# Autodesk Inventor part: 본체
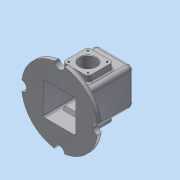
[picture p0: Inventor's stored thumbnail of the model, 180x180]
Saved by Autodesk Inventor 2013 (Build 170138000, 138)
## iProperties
Created: 2018-07
Part Number: 본체
Material: 알루미늄 6061
Document SubType Name: Modeling
Designer: Administrator
Density: 2.71 g/cm^3
Mass: 931.22 g
Surface Area: 1021.53 cm^2
Volume: 343.623 cm^3
Author: Administrator
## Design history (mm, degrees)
sketch "스케치1"
  geometry: C1 r 75 at (0, 0); 1 further point
  constraints: 1 centre point, 1 coincident
  dimensions: "d0" = 150 diameter of C1
extrude "돌출1" new body sketch "스케치1" distance "d1" = 10; taper "d2" = 0 deg
fillet "모깎기1" dims "d9" = 3
sketch "스케치2"
  geometry: C1 r 10 at (0, 75); 1 further point
  constraints: 2 vertical alignment, 1 centre point, 1 other
  dimensions: "d3" = 20 diameter of C1
extrude "돌출2" cut sketch "스케치2" distance "d4" = 10; taper "d5" = 0 deg
sketch "스케치3"
  geometry: L1 (-37, 37)-(37, 37); L2 (37, 37)-(37, -37); L3 (37, -37)-(-37, -37); L4 (-37, -37)-(-37, 37); A1 r 72 centre (0, 0) between (71.393, 9.327) and (9.327, 71.393) reference; A2 r 72 centre (0, 0) between (9.327, -71.393) and (71.393, -9.327) reference; 2 further points
  constraints: 8 end point, 2 midpoint, 2 parallel, 1 horizontal, 1 horizontal alignment, 1 perpendicular, 1 vertical alignment
  dimensions: "d10" = 74 distance of L1.start L1.end; "d12" = 74 distance of L1.end L2.end
extrude "돌출3" join sketch "스케치3" distance "d13" = 100; taper "d14" = 0 deg
sketch "스케치4"
  geometry: L1 (37, 37)-(-37, 37) reference; L2 (37, -37)-(37, 37) reference; L3 (-37, 37)-(-37, -37) reference; L4 (-37, -37)-(37, -37) reference; L5 (-32, 32)-(32, 32); L6 (32, 32)-(32, -32); L7 (32, -32)-(-32, -32); L8 (-32, -32)-(-32, 32)
  constraints: 8 end point, 3 other
  dimensions: "d15" = 5 distance between parallel lines of L1 L5
extrude "돌출4" cut sketch "스케치4" distance "d16" = 105; taper "d17" = 0 deg
fillet "모깎기2" dims "d18" = 8, "d19" = 3
sketch "스케치5"
  geometry: L1 (4, 71)-(54, 71); L2 (54, 71)-(54, 21); L3 (54, 21)-(4, 21); L4 (4, 21)-(4, 71); L5 (58, 100)-(0, 100) reference; L6 (66, 0)-(66, 92) reference; 5 further points
  constraints: 8 end point, 4 midpoint, 2 parallel, 1 horizontal, 1 horizontal alignment, 1 perpendicular, 1 vertical alignment
  dimensions: "d20" = 50 distance of L1.start L1.end; "d22" = 50 distance of L1.end L2.end
extrude "돌출5" join sketch "스케치5" distance "d23" = 13; taper "d24" = 0 deg
sketch "스케치6"
  geometry: L1 (4, 81)-(54, 81) reference; L2 (54, 81)-(54, 31) reference; L3 (54, 31)-(4, 31) reference; L4 (4, 31)-(4, 81) reference; L5 (4, 81)-(54, 81); L6 (54, 81)-(54, 31); L7 (54, 31)-(4, 31); L8 (4, 31)-(4, 81); 1 further point
  constraints: 8 end point, 2 parallel, 1 horizontal, 1 perpendicular
extrude "돌출6" join sketch "스케치6" distance "d25" = 7; taper "d26" = -20 deg
sketch "스케치7"
  geometry: L1 (54, 71)-(4, 71) reference; L2 (54, 21)-(54, 71) reference; C1 r 16 at (29, 46); 3 further points
  constraints: 2 midpoint, 1 centre point, 1 horizontal alignment, 1 vertical alignment
  dimensions: "d27" = 32 diameter of C1
extrude "돌출7" cut sketch "스케치7" stored distance "d28" = 7; taper "d29" = 0 deg
chamfer "모따기1" distance "d30" = 1; stored, may be unused: second distance "d31" = 2, angle "d32" = 45 deg
fillet "모깎기3" dims "d33" = 6, "d34" = 3
hole "구멍1" diameter "d37" = 3.242; stored, may be unused: countersink angle "d41" = 90 deg, drill point angle "d43" = 118 deg; dims "d35" = 10, "d36" = 10, "d38" = 8, "d39" = 4, "d40" = 2, "d42" = 10
fillet "모깎기4" dims "d47" = 3
sketch "스케치8"
  geometry: L1 (-20, 20)-(20, 20); L2 (20, 20)-(20, -20); L3 (20, -20)-(-20, -20); L4 (-20, -20)-(-20, 20); 3 further points
  constraints: 8 end point, 2 midpoint, 2 parallel, 1 horizontal, 1 horizontal alignment, 1 perpendicular, 1 vertical alignment
  dimensions: "d48" = 40 distance of L1.start L1.end; "d50" = 40 distance of L1.end L2.end
extrude "돌출8" join sketch "스케치8" distance "d51" = 7; taper "d52" = 0 deg
sketch "스케치9"
  geometry: C1 r 17.5 at (0, 0); 1 further point
  constraints: 1 centre point, 1 coincident
  dimensions: "d53" = 35 diameter of C1
extrude "돌출9" join sketch "스케치9" distance "d54" = 3; taper "d55" = 0 deg
fillet "모깎기5" dims "d56" = 3
hole "구멍2" diameter "d59" = 21; stored, may be unused: countersink angle "d63" = 90 deg, drill point angle "d65" = 0 deg; dims "d57" = 10, "d58" = 10, "d60" = 8, "d61" = 28, "d62" = 4, "d64" = 21
fillet "모깎기6" dims "d66" = 3
sketch "스케치10"
  geometry: L1 (66, -89)-(66, 0) reference; L2 (46.5, 18)-(11.5, 18) reference; 2 further points
  constraints: 1 other
  dimensions: "d67" = 37 distance from line of point (29, -12) L1; "d68" = 30 distance from line of L2 point (29, -12)
feature "엠보싱1" sketch "스케치10" dims "d69" = 0.5, "d70" = 0
node "솔리드1"
pattern_circular "원형 패턴1" dims angle "d7" = 360 deg
pattern_circular "원형 패턴2" dims angle "d45" = 360 deg
mirror "대칭1"
node "투영된 루프1"
